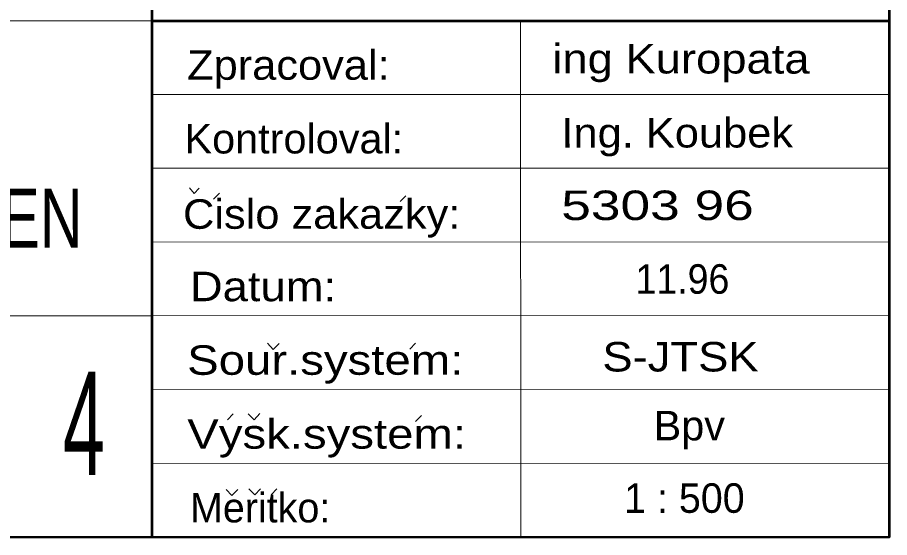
# Model space of a CAD drawing. Extents: x -670514 to -669423, y -1130798 to -1130123.
# Drawn here: x -670362.9 to -670339.25, y -1130263.7 to -1130249.6 of the extents above; entities that cross this region are included whole.
import ezdxf
from ezdxf.enums import TextEntityAlignment as Align

# ---------------------------------------------------------------- set-up
doc = ezdxf.new("R2010")
doc.units = 0
doc.header["$LTSCALE"] = 0.24
doc.layers.add('61', color=7, linetype='Continuous', lineweight=13)

msp = doc.modelspace()

# ---------------------------------------------------------------- linework, layer by layer
at = {"layer": '61', "lineweight": 53}
for p, q in [((-670359.244, -1130263.688), (-670359.249, -1130243.686)), ((-670359.248, -1130249.687), (-670339.251, -1130249.684))]:
    msp.add_line(p, q, dxfattribs=at)
at = {"layer": '61'}
for p, q in [((-670399.248, -1130249.695), (-670359.248, -1130249.687)), ((-670349.251, -1130249.683), (-670349.247, -1130263.686)), ((-670359.251, -1130251.687), (-670339.247, -1130251.684)), ((-670359.245, -1130253.686), (-670339.249, -1130253.685)), ((-670358.234, -1130254.219), (-670358.101, -1130254.37)), ((-670357.969, -1130254.221), (-670358.101, -1130254.37)), ((-670357.577, -1130254.526), (-670357.421, -1130254.36)), ((-670352.518, -1130254.591), (-670352.361, -1130254.431)), ((-670359.248, -1130255.687), (-670339.249, -1130255.684)), ((-670399.248, -1130257.699), (-670359.25, -1130257.689)), ((-670359.25, -1130257.689), (-670339.247, -1130257.681)), ((-670352.26, -1130258.595), (-670352.104, -1130258.431)), ((-670359.245, -1130259.687), (-670339.246, -1130259.68)), ((-670357.203, -1130260.508), (-670357.046, -1130260.342)), ((-670352.102, -1130260.555), (-670351.942, -1130260.393)), ((-670359.245, -1130261.689), (-670339.246, -1130261.685)), ((-670356.017, -1130262.542), (-670355.861, -1130262.375))]:
    msp.add_line(p, q, dxfattribs=at)
at = {"layer": '61', "lineweight": 53}
msp.add_lwpolyline([(-670399.245, -1130263.7), (-670339.248, -1130263.681), (-670339.249, -1130243.684), (-670399.248, -1130243.696)], close=True, dxfattribs=at)
at = {"layer": '61'}
for points in [[(-670355.802, -1130258.434), (-670355.958, -1130258.598), (-670356.117, -1130258.43)], [(-670356.323, -1130260.34), (-670356.481, -1130260.51), (-670356.637, -1130260.346)], [(-670356.921, -1130262.397), (-670357.079, -1130262.557), (-670357.235, -1130262.397)], [(-670356.303, -1130262.382), (-670356.463, -1130262.543), (-670356.62, -1130262.382)]]:
    msp.add_lwpolyline(points, dxfattribs=at)

# ---------------------------------------------------------------- texts
for s, height, rotation, width, p in [('Zpracoval:', 0.8, 0.014, 1.1, (-670358.296, -1130251.286)), ('Ing. Koubek', 0.8, 0.015, 1.1, (-670348.144, -1130253.124)), ('Kontroloval:', 0.8, 0.014, 1.05, (-670358.367, -1130253.285)), ('PROPOJENI   KOTELEN', 1.599, 0.009, 0.75, (-670379.22, -1130255.841)), ('5303 96', 0.8, 0.015, 1.35, (-670348.149, -1130255.091)), ('Cislo zakazky:', 0.8, 0.014, 1.1, (-670358.407, -1130255.327)), ('11.96', 0.8, 0.015, 0.95, (-670346.134, -1130257.089)), ('Datum:', 0.8, 0.014, 1.15, (-670358.22, -1130257.291)), ('Sour.system:', 0.8, 0.014, 1.2, (-670358.295, -1130259.287)), ('Vysk.system:', 0.8, 0.014, 1.2, (-670358.292, -1130261.29))]:
    msp.add_text(s, height=height, rotation=rotation, dxfattribs=dict(at, width=width)).set_placement(p)
for s, height, rotation, width, p in [('ing Kuropata', 0.8, 359.935, 1.15, (-670344.9035, -1130251.1153)), ('S-JTSK', 0.8, 0.014, 1.15, (-670344.9151, -1130259.1965)), ('4', 2.8, 0.009, 0.55, (-670361.0942, -1130262.0039)), ('Bpv', 0.8, 0.014, 1.05, (-670344.6771, -1130261.0638))]:
    msp.add_text(s, height=height, rotation=rotation, dxfattribs=dict(at, width=width)).set_placement(p, align=Align.CENTER)
msp.add_text('1 : 500', height=0.8, rotation=0.014, dxfattribs=at).set_placement((-670344.8101, -1130263.0295), align=Align.CENTER)
msp.add_text('Meritko:', height=0.8, rotation=0.014, dxfattribs=at).set_placement((-670358.217, -1130263.29))

doc.saveas('drawing.dxf')
